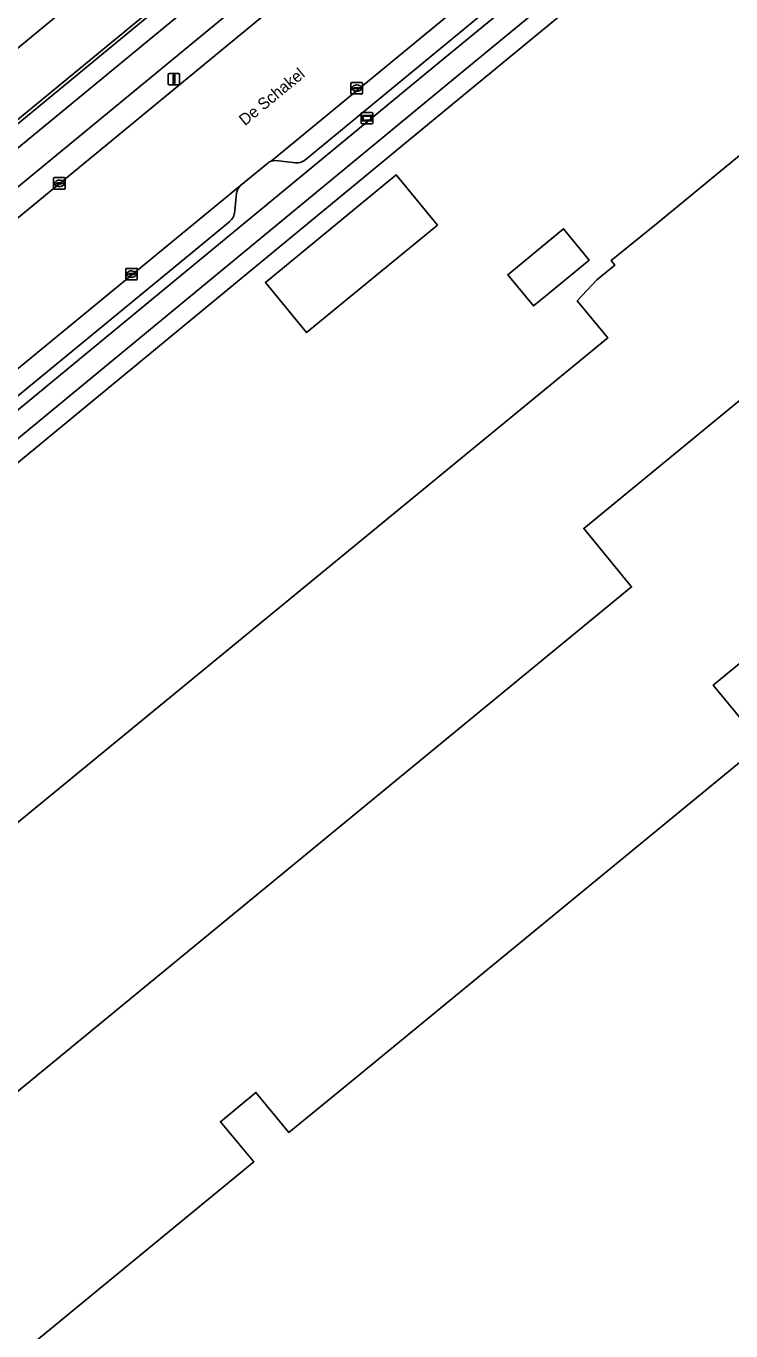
# Model space of a CAD drawing. Extents: x 156141 to 158132, y 385651 to 388333.
# Drawn here: x 157358.7 to 157419.6, y 386478.5 to 386591.2 of the extents above; entities that cross this region are included whole.
import ezdxf

# ---------------------------------------------------------------- set-up
doc = ezdxf.new("R2010")
doc.units = 0
for name, color, linetype in [('IMGEO_Berm_groen', 7, 'Continuous'), ('IMGEO_Berm_open', 7, 'Continuous'), ('IMGEO_Erf', 7, 'Continuous'), ('IMGEO_Fietspad_gesloten', 7, 'Continuous'), ('IMGEO_Hek', 7, 'Continuous'), ('IMGEO_Informatiebord', 7, 'Continuous'), ('IMGEO_Kolk', 7, 'Continuous'), ('IMGEO_Lichtmast', 7, 'Continuous'), ('IMGEO_Openbare_ruimte_label', 7, 'Continuous'), ('IMGEO_Pand', 7, 'Continuous'), ('IMGEO_Parkeervlak_open', 7, 'Continuous'), ('IMGEO_Rijbaan_lokaal_gesloten', 7, 'Continuous'), ('IMGEO_Rijbaan_lokaal_open', 7, 'Continuous'), ('IMGEO_Voetpad_open', 7, 'Continuous')]:
    doc.layers.add(name, color=color, linetype=linetype)

msp = doc.modelspace()

# ---------------------------------------------------------------- linework, layer by layer
at = {"layer": 'IMGEO_Berm_groen'}
msp.add_lwpolyline([(157382.6, 386594.94), (157381.27, 386596.54), (157296.44, 386526.68), (157297.77, 386525.08)], close=True, dxfattribs=at)
at = {"layer": 'IMGEO_Berm_open'}
for points in [[(157394.44, 386588.13), (157418.23, 386607.64), (157416.93, 386607.77), (157382.77, 386579.63)], [(157328.05, 386533.38), (157394.44, 386588.13)], [(157382.01, 386579.41), (157380.31, 386579.62), (157379.88, 386579.57)], [(157379.61, 386579.4), (157377.25, 386577.46)], [(157376.91, 386576.81), (157376.72, 386575.02)], [(157376.34, 386574.37), (157372.41, 386571.12), (157327.56, 386534.29)]]:
    msp.add_lwpolyline(points, dxfattribs=at)
for centre, radius, start, end in [((157380.17, 386578.81), 0.808, 110.9255, 133.5453), ((157382.11, 386580.47), 1.06, 264.3959, 307.9554), ((157377.86, 386576.72), 0.958, 129.7412, 174.3824), ((157375.54, 386575.26), 1.19, 311.7309, 348.629)]:
    msp.add_arc(centre, radius, start, end, dxfattribs=at)
at = {"layer": 'IMGEO_Erf'}
for points in [[(157426, 386606.55), (157415.89, 386601.23), (157395.72, 386584.6), (157331.08, 386531.34)], [(157374.79, 386603.21), (157247.85, 386498.57)], [(157227.04, 386499.66), (157223.8, 386503.61), (157223.42, 386503.29), (157220.03, 386500.5), (157216.85, 386504.35), (157216.73, 386504.5), (157208.03, 386497.24), (157213.1, 386491.07), (157226.61, 386474.61), (157226.82, 386474.79), (157233.89, 386480.6), (157236.03, 386482.36), (157257.45, 386500), (157293.78, 386529.91), (157370.16, 386592.8)], [(157297.7, 386472.96), (157408.99, 386564.29), (157406.35, 386567.5), (157408.05, 386569.3), (157409.6, 386570.57), (157409.3, 386570.98), (157413.22, 386574.15), (157432.07, 386589.67)], [(157442.52, 386577.05), (157406.91, 386547.83), (157411.05, 386542.77), (157300.91, 386452.3)], [(157318.4, 386443.78), (157378.38, 386493.09), (157375.51, 386496.55), (157378.57, 386499.08), (157381.43, 386495.61), (157386.77, 386500), (157422.31, 386529.18), (157418.11, 386534.29), (157418.24, 386534.39), (157426.03, 386540.78)]]:
    msp.add_lwpolyline(points, dxfattribs=at)
for points in [[(157394.27, 386574.04), (157382.95, 386564.75), (157379.4, 386569.08), (157390.71, 386578.37)], [(157407.39, 386571.02), (157403.78, 386568.05), (157402.56, 386567.05), (157400.35, 386569.75), (157405.17, 386573.72)]]:
    msp.add_lwpolyline(points, close=True, dxfattribs=at)
at = {"layer": 'IMGEO_Fietspad_gesloten'}
for points in [[(157329.52, 386532.12), (157395.18, 386586.24), (157420.83, 386607.38), (157421.75, 386607.26), (157440.24, 386622.34), (157440.35, 386623.46), (157455.22, 386635.71), (157460.75, 386640.33), (157459.61, 386641.71), (157440.56, 386626.13), (157436.32, 386622.67), (157424.34, 386612.8), (157418.23, 386607.64), (157394.44, 386588.13), (157328.05, 386533.38)], [(157264.04, 386500), (157296.44, 386526.68), (157381.27, 386596.54), (157379.64, 386598.54), (157294.79, 386528.69), (157259.95, 386500), (157236.74, 386480.89), (157225.9, 386471.96), (157216.57, 386464.31), (157144.79, 386405.24)]]:
    msp.add_lwpolyline(points, dxfattribs=at)
at = {"layer": 'IMGEO_Hek'}
msp.add_lwpolyline([(157370.51, 386593.46), (157256.85, 386500)], dxfattribs=at)
at = {"layer": 'IMGEO_Informatiebord'}
for p, q in [((157387.68, 386582.88), (157387.68, 386583.68)), ((157387.68, 386583.68), (157387.68, 386582.88)), ((157387.78, 386583.78), (157388.57, 386583.78)), ((157388.57, 386583.78), (157387.78, 386583.78)), ((157388.67, 386583.68), (157388.67, 386582.88)), ((157388.67, 386582.88), (157388.67, 386583.68)), ((157388.57, 386582.78), (157387.78, 386582.78)), ((157387.78, 386582.78), (157388.57, 386582.78))]:
    msp.add_line(p, q, dxfattribs=at)
for points in [[(157387.78, 386583.51), (157388.57, 386583.51), (157388.57, 386583.04), (157387.78, 386583.04), (157387.78, 386583.51)], [(157387.85, 386583.44), (157387.85, 386583.11), (157388.51, 386583.11), (157388.51, 386583.44), (157387.85, 386583.44)]]:
    msp.add_lwpolyline(points, dxfattribs=at)
for centre, start, end in [((157387.78, 386583.68), 90, 180), ((157387.78, 386583.68), 90, 180), ((157388.57, 386583.68), 0, 90), ((157388.57, 386583.68), 360, 90), ((157387.78, 386582.88), 180, 270), ((157387.78, 386582.88), 180, 270), ((157388.57, 386582.88), 270, 0), ((157388.57, 386582.88), 270, 0)]:
    msp.add_arc(centre, 0.1, start, end, dxfattribs=at)
at = {"layer": 'IMGEO_Kolk'}
for p, q in [((157386.86, 386586.37), (157387.72, 386586.37)), ((157386.79, 386585.44), (157386.79, 386586.3)), ((157387.72, 386585.37), (157386.86, 386585.37)), ((157387.05, 386585.86), (157387.05, 386585.88)), ((157387.09, 386585.91), (157387.49, 386585.91)), ((157387.48, 386585.83), (157387.09, 386585.83)), ((157387.3, 386585.59), (157387.27, 386585.59)), ((157387.28, 386586.15), (157387.3, 386586.15)), ((157387.53, 386585.88), (157387.53, 386585.86)), ((157387.79, 386586.3), (157387.79, 386585.44)), ((157361.08, 386577.21), (157361.08, 386578.06)), ((157361.15, 386578.14), (157362.01, 386578.14)), ((157361.34, 386577.63), (157361.34, 386577.64)), ((157361.38, 386577.68), (157361.78, 386577.68)), ((157361.78, 386577.59), (157361.38, 386577.59)), ((157361.59, 386577.36), (157361.56, 386577.36)), ((157361.57, 386577.92), (157361.59, 386577.92)), ((157361.82, 386577.64), (157361.82, 386577.63)), ((157362.08, 386578.06), (157362.08, 386577.21)), ((157362.01, 386577.14), (157361.15, 386577.14)), ((157367.32, 386569.38), (157367.32, 386570.23)), ((157367.4, 386570.3), (157368.25, 386570.3)), ((157367.58, 386569.8), (157367.58, 386569.81)), ((157367.62, 386569.85), (157368.02, 386569.85)), ((157368.02, 386569.76), (157367.62, 386569.76)), ((157367.81, 386570.08), (157367.84, 386570.08)), ((157367.83, 386569.52), (157367.81, 386569.52)), ((157368.07, 386569.81), (157368.07, 386569.8)), ((157368.32, 386570.23), (157368.32, 386569.38)), ((157368.25, 386569.3), (157367.4, 386569.3))]:
    msp.add_line(p, q, dxfattribs=at)
for points in [[(157386.86, 386586.37), (157387.72, 386586.37)], [(157386.79, 386585.44), (157386.79, 386586.3)], [(157387.72, 386585.37), (157386.86, 386585.37)], [(157387.79, 386586.3), (157387.79, 386585.44)], [(157361.08, 386577.21), (157361.08, 386578.06)], [(157361.15, 386578.14), (157362.01, 386578.14)], [(157362.08, 386578.06), (157362.08, 386577.21)], [(157362.01, 386577.14), (157361.15, 386577.14)], [(157367.32, 386569.38), (157367.32, 386570.23)], [(157367.4, 386570.3), (157368.25, 386570.3)], [(157368.32, 386570.23), (157368.32, 386569.38)], [(157368.25, 386569.3), (157367.4, 386569.3)]]:
    msp.add_lwpolyline(points, dxfattribs=at)
for centre, radius, start, end in [((157386.86, 386586.29), 0.0765, 91.552, 178.448), ((157386.86, 386586.29), 0.0765, 91.552, 178.448), ((157387.71, 386586.29), 0.0765, 1.552, 88.448), ((157387.71, 386586.29), 0.0765, 1.552, 88.448), ((157386.86, 386585.44), 0.0765, 181.552, 268.448), ((157386.86, 386585.44), 0.0765, 181.552, 268.448), ((157387.09, 386585.87), 0.0403, 85.8775, 175.7526), ((157387.08, 386585.86), 0.0366, 178.938, 274.7102), ((157387.49, 386585.87), 0.043, 264.8664, 352.4533), ((157387.49, 386585.87), 0.0386, 1.7309, 96.639), ((157387.71, 386585.44), 0.0765, 271.552, 358.448), ((157387.71, 386585.44), 0.0765, 271.552, 358.448), ((157361.16, 386578.06), 0.0765, 91.552, 178.448), ((157361.16, 386578.06), 0.0765, 91.552, 178.448), ((157361.38, 386577.64), 0.0403, 85.8775, 175.7526), ((157361.37, 386577.63), 0.0366, 178.938, 274.7102), ((157361.78, 386577.64), 0.0386, 1.7309, 96.639), ((157361.78, 386577.64), 0.043, 264.8664, 352.4533), ((157362, 386578.06), 0.0765, 1.552, 88.448), ((157362, 386578.06), 0.0765, 1.552, 88.448), ((157361.16, 386577.21), 0.0765, 181.552, 268.448), ((157361.16, 386577.21), 0.0765, 181.552, 268.448), ((157362, 386577.21), 0.0765, 271.552, 358.448), ((157362, 386577.21), 0.0765, 271.552, 358.448), ((157367.4, 386570.23), 0.0765, 91.552, 178.448), ((157367.4, 386570.23), 0.0765, 91.552, 178.448), ((157367.62, 386569.81), 0.0403, 85.8775, 175.7526), ((157367.62, 386569.8), 0.0366, 178.938, 274.7102), ((157368.03, 386569.81), 0.0386, 1.7309, 96.639), ((157368.02, 386569.8), 0.043, 264.8664, 352.4533), ((157368.25, 386570.23), 0.0765, 1.552, 88.448), ((157368.25, 386570.23), 0.0765, 1.552, 88.448), ((157367.4, 386569.38), 0.0765, 181.552, 268.448), ((157367.4, 386569.38), 0.0765, 181.552, 268.448), ((157368.25, 386569.38), 0.0765, 271.552, 358.448), ((157368.25, 386569.38), 0.0765, 271.552, 358.448)]:
    msp.add_arc(centre, radius, start, end, dxfattribs=at)
for centre, major_axis, ratio, start_param, end_param in [((157387.28, 386585.87), (-0.387, 0.002), 0.722429, 4.712389, 7.853982), ((157387.3, 386585.87), (-0.39, 0.002), 0.717154, 1.570796, 4.712389), ((157361.57, 386577.64), (-0.387, 0.002), 0.722429, 4.712389, 7.853982), ((157361.59, 386577.64), (-0.39, 0.002), 0.717154, 1.570796, 4.712389), ((157367.81, 386569.8), (-0.387, 0.002), 0.722429, 4.712389, 7.853982), ((157367.83, 386569.8), (-0.39, 0.002), 0.717154, 1.570796, 4.712389)]:
    msp.add_ellipse(centre, major_axis=major_axis, ratio=ratio, start_param=start_param, end_param=end_param, dxfattribs=at)
at = {"layer": 'IMGEO_Lichtmast'}
for p, q in [((157370.99, 386586.25), (157370.99, 386587.05)), ((157370.99, 386587.05), (157370.99, 386586.25)), ((157371.09, 386587.15), (157371.88, 386587.15)), ((157371.88, 386587.15), (157371.09, 386587.15)), ((157371.98, 386587.05), (157371.98, 386586.25)), ((157371.98, 386586.25), (157371.98, 386587.05)), ((157371.88, 386586.15), (157371.09, 386586.15)), ((157371.09, 386586.15), (157371.88, 386586.15))]:
    msp.add_line(p, q, dxfattribs=at)
msp.add_lwpolyline([(157371.41, 386587.03), (157371.56, 386587.03), (157371.56, 386586.28), (157371.41, 386586.28), (157371.41, 386587.03)], dxfattribs=at)
for centre, start, end in [((157371.09, 386587.05), 90, 180), ((157371.09, 386587.05), 90, 180), ((157371.88, 386587.05), 0, 90), ((157371.88, 386587.05), 360, 90), ((157371.09, 386586.25), 180, 270), ((157371.09, 386586.25), 180, 270), ((157371.88, 386586.25), 270, 0), ((157371.88, 386586.25), 270, 0)]:
    msp.add_arc(centre, 0.1, start, end, dxfattribs=at)
at = {"layer": 'IMGEO_Pand'}
for points in [[(157394.27, 386574.04), (157390.71, 386578.37), (157379.4, 386569.08), (157382.95, 386564.75)], [(157400.35, 386569.75), (157402.56, 386567.05), (157403.78, 386568.05), (157407.39, 386571.02), (157405.17, 386573.72)]]:
    msp.add_lwpolyline(points, close=True, dxfattribs=at)
msp.add_lwpolyline([(157426.03, 386540.78), (157418.24, 386534.39), (157418.11, 386534.29), (157422.31, 386529.18), (157386.77, 386500), (157381.43, 386495.61), (157378.57, 386499.08), (157375.51, 386496.55), (157378.38, 386493.09), (157318.4, 386443.78), (157315.55, 386447.27), (157312.48, 386444.77), (157313.51, 386443.51), (157305.06, 386436.63), (157296.7, 386446.84), (157262.78, 386418.97), (157291.47, 386384.05), (157295.33, 386387.23), (157320.05, 386407.56), (157320.38, 386407.15), (157324.29, 386410.39), (157351.69, 386377.03), (157353.51, 386374.81), (157349.15, 386371.23)], dxfattribs=at)
at = {"layer": 'IMGEO_Parkeervlak_open'}
for points in [[(157377.25, 386577.46), (157325.99, 386535.33), (157321.81, 386531.73), (157317.23, 386527.67), (157305.01, 386516.28), (157287.58, 386500), (157249.93, 386464.85), (157230.04, 386446.32)], [(157376.72, 386575.02), (157376.91, 386576.81)], [(157327.56, 386534.29), (157372.41, 386571.12), (157376.34, 386574.37)]]:
    msp.add_lwpolyline(points, dxfattribs=at)
for centre, radius, start, end in [((157377.86, 386576.72), 0.958, 129.7412, 174.3824), ((157375.54, 386575.26), 1.19, 311.7309, 348.629)]:
    msp.add_arc(centre, radius, start, end, dxfattribs=at)
at = {"layer": 'IMGEO_Rijbaan_lokaal_gesloten'}
for points in [[(157379.88, 386579.57), (157414.53, 386608.12), (157441.01, 386630.01), (157441.95, 386630.8), (157455.25, 386641.7), (157459.29, 386645.03), (157456.36, 386648.41), (157452.12, 386644.95)], [(157429.51, 386633.55), (157391.76, 386602.48), (157387.24, 386598.76), (157382.6, 386594.94), (157297.77, 386525.08), (157267.32, 386500), (157239.52, 386477.11)], [(157247.85, 386498.57), (157374.79, 386603.21)], [(157432.07, 386589.67), (157413.22, 386574.15), (157409.3, 386570.98), (157409.6, 386570.57), (157408.05, 386569.3), (157406.35, 386567.5), (157408.99, 386564.29), (157297.7, 386472.96)], [(157287.58, 386500), (157305.01, 386516.28), (157317.23, 386527.67), (157321.81, 386531.73), (157325.99, 386535.33), (157377.25, 386577.46), (157379.61, 386579.4)], [(157349.15, 386371.23), (157353.51, 386374.81), (157351.69, 386377.03), (157334.39, 386362.79), (157307.29, 386395.73), (157295.84, 386386.36), (157291.56, 386382.8), (157261.17, 386419.76), (157281.8, 386436.65), (157297.18, 386449.23), (157295.71, 386451.03), (157299.46, 386454.04), (157300.91, 386452.3), (157411.05, 386542.77), (157406.91, 386547.83), (157442.52, 386577.05)]]:
    msp.add_lwpolyline(points, dxfattribs=at)
msp.add_arc((157380.17, 386578.81), 0.808, 110.9255, 133.5453, dxfattribs=at)
at = {"layer": 'IMGEO_Rijbaan_lokaal_open'}
for points in [[(157416.93, 386607.77), (157414.53, 386608.12), (157379.88, 386579.57), (157380.31, 386579.62), (157382.01, 386579.41)], [(157382.77, 386579.63), (157416.93, 386607.77)]]:
    msp.add_lwpolyline(points, dxfattribs=at)
msp.add_arc((157382.11, 386580.47), 1.06, 264.3959, 307.9554, dxfattribs=at)
at = {"layer": 'IMGEO_Voetpad_open'}
for points in [[(157395.72, 386584.6), (157415.89, 386601.23), (157426, 386606.55), (157426.05, 386606.59), (157426.2, 386606.71), (157421.75, 386607.26), (157420.83, 386607.38), (157395.18, 386586.24), (157329.52, 386532.12)], [(157331.08, 386531.34), (157395.72, 386584.6)]]:
    msp.add_lwpolyline(points, dxfattribs=at)
msp.add_lwpolyline([(157379.64, 386598.54), (157378.62, 386599.78), (157370.16, 386592.8), (157293.78, 386529.91), (157257.45, 386500), (157236.03, 386482.36), (157233.89, 386480.6), (157226.82, 386474.79), (157226.61, 386474.61), (157224.92, 386473.22), (157225.9, 386471.96), (157236.74, 386480.89), (157259.95, 386500), (157294.79, 386528.69)], close=True, dxfattribs=at)

# ---------------------------------------------------------------- texts
at = {"layer": 'IMGEO_Openbare_ruimte_label'}
msp.add_text('De Schakel', height=1, rotation=39.4829, dxfattribs=at).set_placement((157377.62, 386582.58))

doc.saveas('drawing.dxf')
